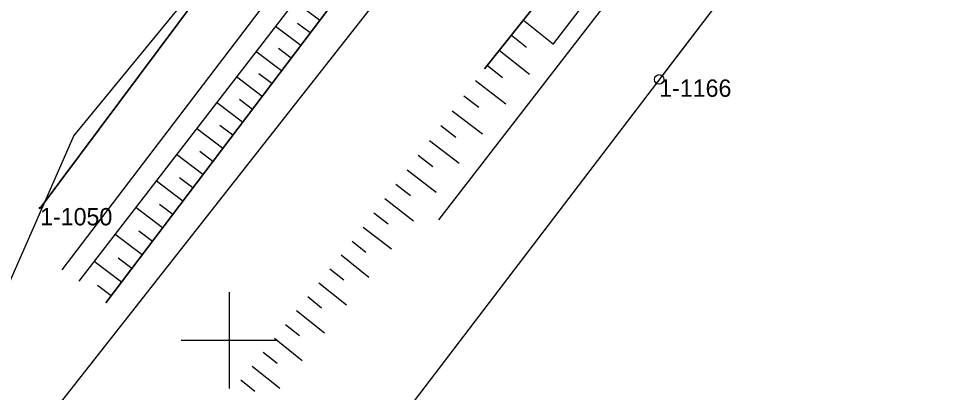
# Model space of a CAD drawing. Extents: x 5598798 to 5599616, y 5661498 to 5662453.
# Drawn here: x 5599039.06 to 5599087.14, y 5661547.29 to 5661566.69 of the extents above; entities that cross this region are included whole.
import ezdxf

# ---------------------------------------------------------------- set-up
doc = ezdxf.new("R2010")
doc.units = 0
for name, color, linetype in [('BUBZ_L_1', 7, 'Continuous'), ('Dzialki', 7, 'Continuous'), ('Kontury', 7, 'Continuous'), ('KTJZ_L_0', 7, 'Continuous'), ('Numery_punktow', 7, 'Continuous'), ('Podzial_sekcyjny_krzyze', 7, 'Continuous'), ('PTRW_L_1', 7, 'Continuous'), ('Punkty', 7, 'Continuous'), ('SUPW_L_0', 7, 'Continuous'), ('Uzytki', 7, 'Continuous')]:
    doc.layers.add(name, color=color, linetype=linetype)

# ---------------------------------------------------------------- blocks, each defined once
blk = doc.blocks.new('GRT')
blk.add_circle((0, 0), 0.25)
blk = doc.blocks.new('GRO')
blk.add_circle((0, 0), 0.045)

msp = doc.modelspace()

# ---------------------------------------------------------------- linework, layer by layer
at = {"layer": 'BUBZ_L_1'}
for p, q in [((5599065.807304, 5661583.70311), (5599042.195012, 5661553.064547)), ((5599043.59456, 5661551.937133), (5599066.813154, 5661582.630911)), ((5599076.678362, 5661580.924495), (5599063.229428, 5661564.085129)), ((5599066.809784, 5661565.376446), (5599077.9025, 5661579.911014)), ((5599054.683505, 5661566.596144), (5599053.382122, 5661567.580587)), ((5599065.246291, 5661566.610436), (5599066.802654, 5661565.367431)), ((5599053.696852, 5661565.29184), (5599052.383758, 5661566.285142)), ((5599054.191283, 5661565.945452), (5599053.537671, 5661566.439884)), ((5599064.623302, 5661565.830394), (5599065.403345, 5661565.207405)), ((5599053.200201, 5661564.635293), (5599052.540706, 5661565.134173)), ((5599063.998823, 5661565.048485), (5599065.562639, 5661563.799527)), ((5599052.70132, 5661563.975798), (5599051.37641, 5661564.978039)), ((5599063.37285, 5661564.264707), (5599064.156628, 5661563.638735)), ((5599051.69683, 5661562.647914), (5599050.359997, 5661563.659173)), ((5599052.2002, 5661563.313343), (5599051.534771, 5661563.816713)), ((5599062.761978, 5661563.475574), (5599064.345829, 5661562.260964)), ((5599062.159176, 5661562.689521), (5599062.945229, 5661562.086719)), ((5599050.6833, 5661561.30808), (5599049.334437, 5661562.32844)), ((5599051.1912, 5661561.979497), (5599050.519783, 5661562.487397)), ((5599061.560845, 5661561.909296), (5599063.121293, 5661560.712633)), ((5599049.66065, 5661559.95619), (5599048.299649, 5661560.985732)), ((5599050.17312, 5661560.633649), (5599049.495661, 5661561.146119)), ((5599060.96695, 5661561.134858), (5599061.741389, 5661560.540963)), ((5599060.377459, 5661560.366162), (5599061.914851, 5661559.18718)), ((5599049.145879, 5661559.275689), (5599048.462324, 5661559.792771)), ((5599048.628797, 5661558.592134), (5599047.255549, 5661559.63094)), ((5599059.79234, 5661559.603166), (5599060.555336, 5661559.018046)), ((5599059.211559, 5661558.845828), (5599060.726235, 5661557.684266)), ((5599048.109394, 5661557.90551), (5599047.419688, 5661558.427245)), ((5599047.587659, 5661557.215803), (5599046.202054, 5661558.263958)), ((5599058.635085, 5661558.094106), (5599059.386807, 5661557.517632)), ((5599058.062886, 5661557.347958), (5599059.555181, 5661556.203559)), ((5599046.537152, 5661555.827087), (5599045.139078, 5661556.884674)), ((5599047.063582, 5661556.523), (5599046.367669, 5661557.04943)), ((5599057.494929, 5661556.607343), (5599058.235544, 5661556.039386)), ((5599045.477192, 5661554.425875), (5599044.066536, 5661555.492978)), ((5599046.008359, 5661555.12805), (5599045.306184, 5661555.659217)), ((5599056.931185, 5661555.87222), (5599058.401431, 5661554.74473)), ((5599056.364393, 5661555.145529), (5599057.084093, 5661554.569812)), ((5599044.407693, 5661553.012053), (5599042.984344, 5661554.088759)), ((5599044.94364, 5661553.720547), (5599044.235146, 5661554.256494)), ((5599055.788552, 5661554.425674), (5599057.228262, 5661553.273992)), ((5599055.212587, 5661553.705664), (5599055.932597, 5661553.129699)), ((5599043.86934, 5661552.300378), (5599043.15447, 5661552.841148)), ((5599054.636497, 5661552.985498), (5599056.076829, 5661551.833319)), ((5599054.060284, 5661552.265177), (5599054.780605, 5661551.688964)), ((5599053.483946, 5661551.544701), (5599054.924898, 5661550.392025)), ((5599052.907483, 5661550.824069), (5599053.628115, 5661550.247607)), ((5599052.330896, 5661550.103282), (5599053.772471, 5661548.950108)), ((5599051.754185, 5661549.382339), (5599052.475128, 5661548.805628)), ((5599051.17735, 5661548.661241), (5599052.619546, 5661547.507569)), ((5599050.60039, 5661547.939987), (5599051.321643, 5661547.363027))]:
    msp.add_line(p, q, dxfattribs=at)
at = {"layer": 'Dzialki'}
for p, q in [((5599040.18, 5661556.86), (5599075.49, 5661604.18)), ((5599087.14, 5661583.01), (5599072.29, 5661563.53))]:
    msp.add_line(p, q, dxfattribs=at)
at = {"layer": 'Kontury'}
for p, q in [((5599075.49, 5661604.18), (5599040.18, 5661556.86)), ((5599087.14, 5661583.01), (5599045.53, 5661528.41))]:
    msp.add_line(p, q, dxfattribs=at)
at = {"layer": 'KTJZ_L_0'}
for p, q in [((5599066.81, 5661582.63), (5599043.59, 5661551.94)), ((5599068.11, 5661580.98), (5599036.03, 5661540.16)), ((5599063.23, 5661564.09), (5599076.68, 5661580.92))]:
    msp.add_line(p, q, dxfattribs=at)
at = {"layer": 'Podzial_sekcyjny_krzyze'}
for p, q in [((5599050, 5661547.5), (5599050, 5661552.5)), ((5599047.5, 5661550), (5599052.5, 5661550))]:
    msp.add_line(p, q, dxfattribs=at)
at = {"layer": 'PTRW_L_1'}
for p, q in [((5599041.326774, 5661553.647692), (5599064.730159, 5661584.391797)), ((5599065.807304, 5661583.70311), (5599042.195012, 5661553.064547)), ((5599060.855368, 5661556.243842), (5599078.884868, 5661579.576282))]:
    msp.add_line(p, q, dxfattribs=at)
at = {"layer": 'SUPW_L_0'}
for p, q in [((5599065.428445, 5661589.232718), (5599041.92742, 5661560.625386)), ((5599065.428445, 5661589.232718), (5599041.92742, 5661560.625386)), ((5599041.92742, 5661560.625386), (5599038.151952, 5661551.985555))]:
    msp.add_line(p, q, dxfattribs=at)
at = {"layer": 'Uzytki'}
for p, q in [((5599040.18, 5661556.86), (5599075.49, 5661604.18)), ((5599087.14, 5661583.01), (5599045.53, 5661528.41))]:
    msp.add_line(p, q, dxfattribs=at)

# ---------------------------------------------------------------- block references
at = {"layer": 'Punkty'}
for name, p in [('GRT', (5599072.29, 5661563.53)), ('GRO', (5599040.18, 5661556.86))]:
    msp.add_blockref(name, p, dxfattribs=at)

# ---------------------------------------------------------------- texts
at = {"layer": 'Numery_punktow'}
for s, p in [('1-1166', (5599072.29, 5661562.63)), ('1-1050', (5599040.18, 5661555.96))]:
    msp.add_text(s, height=0.9, dxfattribs=at).set_placement(p)

doc.saveas('drawing.dxf')
